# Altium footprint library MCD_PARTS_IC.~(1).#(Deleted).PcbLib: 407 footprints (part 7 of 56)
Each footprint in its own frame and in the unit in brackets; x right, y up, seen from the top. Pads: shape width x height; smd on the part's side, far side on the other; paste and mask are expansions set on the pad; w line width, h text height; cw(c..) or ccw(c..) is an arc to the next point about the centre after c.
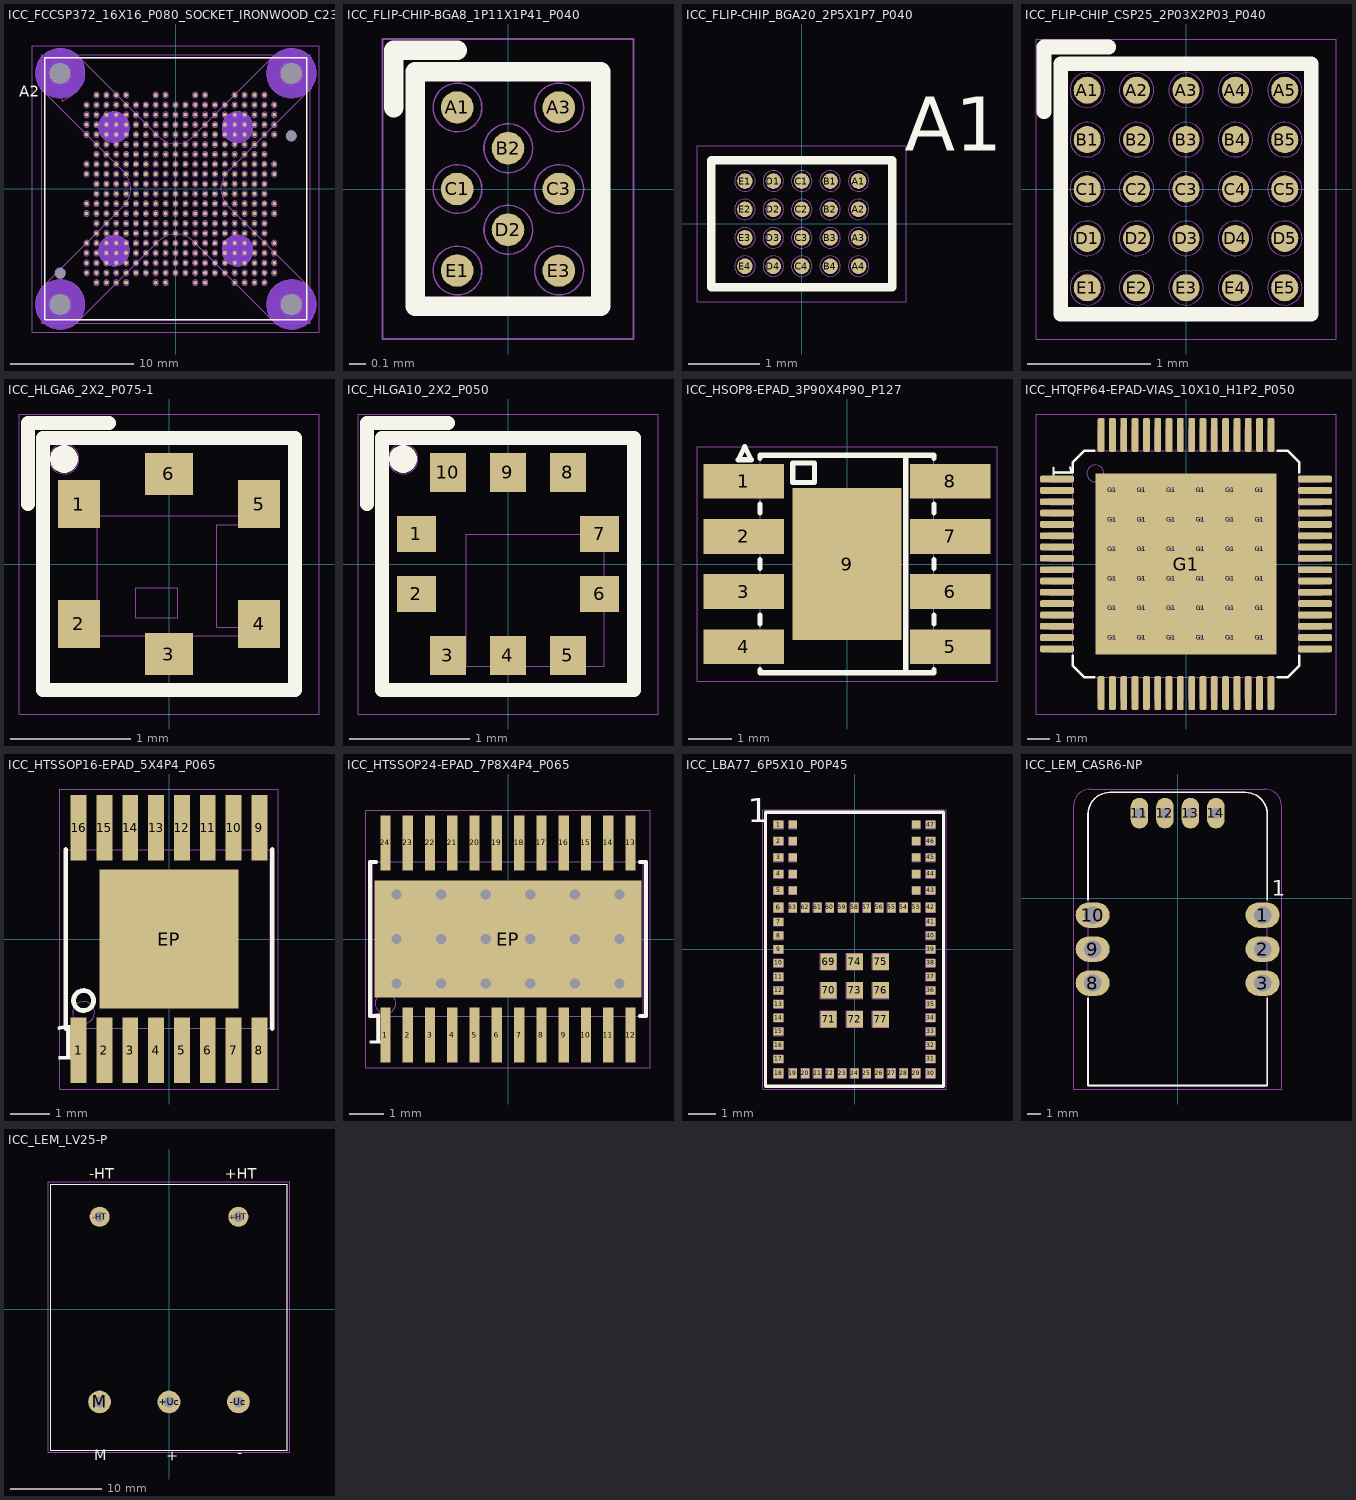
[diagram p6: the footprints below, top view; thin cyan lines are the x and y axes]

## ICC_FCCSP372_16X16_P080_SOCKET_IRONWOOD_C23649 [mm] "MCD-04310"
height 10.13
pads (378):
  round 0.32 smd mask+0.05: A2(-6.425,7.6) A3(-5.625,7.6) A4(-4.825,7.6) A5(-4.025,7.6) A8(-1.625,7.6) A9(-0.825,7.6) A12(1.575,7.6) A13(2.375,7.6) A16(4.775,7.6) A17(5.575,7.6) A18(6.375,7.6) A19(7.175,7.6) B1(-7.225,6.8) B2(-6.425,6.8) B3(-5.625,6.8) B4(-4.825,6.8) B5(-4.025,6.8) B6(-3.225,6.8) B7(-2.425,6.8) B8(-1.625,6.8) B9(-0.825,6.8) B10(-0.025,6.8) B11(0.775,6.8) B12(1.575,6.8) B13(2.375,6.8) B14(3.175,6.8) B15(3.975,6.8) B16(4.775,6.8) B17(5.575,6.8) B18(6.375,6.8) B19(7.175,6.8) B20(7.975,6.8) C1(-7.225,6) C2(-6.425,6) C3(-5.625,6) C4(-4.825,6) C5(-4.025,6) C6(-3.225,6) C7(-2.425,6) C8(-1.625,6) C9(-0.825,6) C10(-0.025,6) C11(0.775,6) C12(1.575,6) C13(2.375,6) C14(3.175,6) C15(3.975,6) C16(4.775,6) C17(5.575,6) C18(6.375,6) C19(7.175,6) C20(7.975,6) D1(-7.225,5.2) D2(-6.425,5.2) D3(-5.625,5.2) D4(-4.825,5.2) D5(-4.025,5.2) D6(-3.225,5.2) D7(-2.425,5.2) D8(-1.625,5.2) D9(-0.825,5.2) D10(-0.025,5.2) D11(0.775,5.2) D12(1.575,5.2) D13(2.375,5.2) D14(3.175,5.2) D15(3.975,5.2) D16(4.775,5.2) D17(5.575,5.2) D18(6.375,5.2) D19(7.175,5.2) D20(7.975,5.2) E1(-7.225,4.4) E2(-6.425,4.4) E3(-5.625,4.4) E4(-4.825,4.4) E5(-4.025,4.4) E6(-3.225,4.4) E7(-2.425,4.4) E8(-1.625,4.4) E9(-0.825,4.4) E10(-0.025,4.4) E11(0.775,4.4) E12(1.575,4.4) E13(2.375,4.4) E14(3.175,4.4) E15(3.975,4.4) E16(4.775,4.4) E17(5.575,4.4) E18(6.375,4.4) E19(7.175,4.4) E20(7.975,4.4) F2(-6.425,3.6) F3(-5.625,3.6) F4(-4.825,3.6) F5(-4.025,3.6) F6(-3.225,3.6) F7(-2.425,3.6) F8(-1.625,3.6) F9(-0.825,3.6) F10(-0.025,3.6) F11(0.775,3.6) F12(1.575,3.6) F13(2.375,3.6) F14(3.175,3.6) F15(3.975,3.6) F16(4.775,3.6) F17(5.575,3.6) F18(6.375,3.6) F19(7.175,3.6) G2(-6.425,2.8) G3(-5.625,2.8) G4(-4.825,2.8) G5(-4.025,2.8) G6(-3.225,2.8) G7(-2.425,2.8) G8(-1.625,2.8) G9(-0.825,2.8) G10(-0.025,2.8) G11(0.775,2.8) G12(1.575,2.8) G13(2.375,2.8) G14(3.175,2.8) G15(3.975,2.8) G16(4.775,2.8) G17(5.575,2.8) G18(6.375,2.8) G19(7.175,2.8) H1(-7.225,2) H2(-6.425,2) H3(-5.625,2) H4(-4.825,2) H5(-4.025,2) H6(-3.225,2) H7(-2.425,2) H8(-1.625,2) H9(-0.825,2) H10(-0.025,2) H11(0.775,2) H12(1.575,2) H13(2.375,2) H14(3.175,2) H15(3.975,2) H16(4.775,2) H17(5.575,2) H18(6.375,2) H19(7.175,2) H20(7.975,2) J1(-7.225,1.2) J2(-6.425,1.2) J3(-5.625,1.2) J4(-4.825,1.2) J5(-4.025,1.2) J6(-3.225,1.2) J7(-2.425,1.2) J8(-1.625,1.2) J9(-0.825,1.2) J10(-0.025,1.2) J11(0.775,1.2) J12(1.575,1.2) J13(2.375,1.2) J14(3.175,1.2) J15(3.975,1.2) J16(4.775,1.2) J17(5.575,1.2) J18(6.375,1.2) J19(7.175,1.2) J20(7.975,1.2) K2(-6.425,0.4) K3(-5.625,0.4) K4(-4.825,0.4) K5(-4.025,0.4) K6(-3.225,0.4) K7(-2.425,0.4) K8(-1.625,0.4) K9(-0.825,0.4) K10(-0.025,0.4) K11(0.775,0.4) K12(1.575,0.4) K13(2.375,0.4) K14(3.175,0.4) K15(3.975,0.4) K16(4.775,0.4) K17(5.575,0.4) K18(6.375,0.4) K19(7.175,0.4) L2(-6.425,-0.4) L3(-5.625,-0.4) L4(-4.825,-0.4) L5(-4.025,-0.4) L6(-3.225,-0.4) L7(-2.425,-0.4) L8(-1.625,-0.4) L9(-0.825,-0.4) L10(-0.025,-0.4) L11(0.775,-0.4) L12(1.575,-0.4) L13(2.375,-0.4) L14(3.175,-0.4) L15(3.975,-0.4) L16(4.775,-0.4) L17(5.575,-0.4) L18(6.375,-0.4) L19(7.175,-0.4) M1(-7.225,-1.2) M2(-6.425,-1.2) M3(-5.625,-1.2) M4(-4.825,-1.2) M5(-4.025,-1.2) M6(-3.225,-1.2) M7(-2.425,-1.2) M8(-1.625,-1.2) M9(-0.825,-1.2) M10(-0.025,-1.2) M11(0.775,-1.2) M12(1.575,-1.2) M13(2.375,-1.2) M14(3.175,-1.2) M15(3.975,-1.2) M16(4.775,-1.2) M17(5.575,-1.2) M18(6.375,-1.2) M19(7.175,-1.2) M20(7.975,-1.2) N1(-7.225,-2) N2(-6.425,-2) N3(-5.625,-2) N4(-4.825,-2) N5(-4.025,-2) N6(-3.225,-2) N7(-2.425,-2) N8(-1.625,-2) N9(-0.825,-2) N10(-0.025,-2) N11(0.775,-2) N12(1.575,-2) N13(2.375,-2) N14(3.175,-2) N15(3.975,-2) N16(4.775,-2) N17(5.575,-2) N18(6.375,-2) N19(7.175,-2) N20(7.975,-2) P2(-6.425,-2.8) P3(-5.625,-2.8) P4(-4.825,-2.8) P5(-4.025,-2.8) P6(-3.225,-2.8) P7(-2.425,-2.8) P8(-1.625,-2.8) P9(-0.825,-2.8) P10(-0.025,-2.8) P11(0.775,-2.8) P12(1.575,-2.8) P13(2.375,-2.8) P14(3.175,-2.8) P15(3.975,-2.8) P16(4.775,-2.8) P17(5.575,-2.8) P18(6.375,-2.8) P19(7.175,-2.8) R2(-6.425,-3.6) R3(-5.625,-3.6) R4(-4.825,-3.6) R5(-4.025,-3.6) R6(-3.225,-3.6) R7(-2.425,-3.6) R8(-1.625,-3.6) R9(-0.825,-3.6) R10(-0.025,-3.6) R11(0.775,-3.6) R12(1.575,-3.6) R13(2.375,-3.6) R14(3.175,-3.6) R15(3.975,-3.6) R16(4.775,-3.6) R17(5.575,-3.6) R18(6.375,-3.6) R19(7.175,-3.6) T1(-7.225,-4.4) T2(-6.425,-4.4) T3(-5.625,-4.4) T4(-4.825,-4.4) T5(-4.025,-4.4) T6(-3.225,-4.4) T7(-2.425,-4.4) T8(-1.625,-4.4) T9(-0.825,-4.4) T10(-0.025,-4.4) T11(0.775,-4.4) T12(1.575,-4.4) T13(2.375,-4.4) T14(3.175,-4.4) T15(3.975,-4.4) T16(4.775,-4.4) T17(5.575,-4.4) T18(6.375,-4.4) T19(7.175,-4.4) T20(7.975,-4.4) U1(-7.225,-5.2) U2(-6.425,-5.2) U3(-5.625,-5.2) U4(-4.825,-5.2) U5(-4.025,-5.2) U6(-3.225,-5.2) U7(-2.425,-5.2) U8(-1.625,-5.2) U9(-0.825,-5.2) U10(-0.025,-5.2) U11(0.775,-5.2) U12(1.575,-5.2) U13(2.375,-5.2) U14(3.175,-5.2) U15(3.975,-5.2) U16(4.775,-5.2) U17(5.575,-5.2) U18(6.375,-5.2) U19(7.175,-5.2) U20(7.975,-5.2) V1(-7.225,-6) V2(-6.425,-6) V3(-5.625,-6) V4(-4.825,-6) V5(-4.025,-6) V6(-3.225,-6) V7(-2.425,-6) V8(-1.625,-6) V9(-0.825,-6) V10(-0.025,-6) V11(0.775,-6) V12(1.575,-6) V13(2.375,-6) V14(3.175,-6) V15(3.975,-6) V16(4.775,-6) V17(5.575,-6) V18(6.375,-6) V19(7.175,-6) V20(7.975,-6) W1(-7.225,-6.8) W2(-6.425,-6.8) W3(-5.625,-6.8) W4(-4.825,-6.8) W5(-4.025,-6.8) W6(-3.225,-6.8) W7(-2.425,-6.8) W8(-1.625,-6.8) W9(-0.825,-6.8) W10(-0.025,-6.8) W11(0.775,-6.8) W12(1.575,-6.8) W13(2.375,-6.8) W14(3.175,-6.8) W15(3.975,-6.8) W16(4.775,-6.8) W17(5.575,-6.8) W18(6.375,-6.8) W19(7.175,-6.8) W20(7.975,-6.8) Y2(-6.425,-7.6) Y3(-5.625,-7.6) Y4(-4.825,-7.6) Y5(-4.025,-7.6) Y8(-1.625,-7.6) Y9(-0.825,-7.6) Y12(1.575,-7.6) Y13(2.375,-7.6) Y16(4.775,-7.6) Y17(5.575,-7.6) Y18(6.375,-7.6) Y19(7.175,-7.6)
  round 0 hole 0.85 unplated mask+0.05: NPTH2(-9.363,-6.823) NPTH2(9.363,4.283)
  round 0 hole 1.71 unplated mask+0.05: PTH1(-9.37,-9.369) PTH1(-9.37,9.356) PTH1(9.355,-9.369) PTH1(9.355,9.356)
Bottom Layer keep-out:
  region: -3.75,5 -3.75,4.877 -3.798,4.635 -3.892,4.408 -4.029,4.203 -4.203,4.029 -4.408,3.892 -4.635,3.798 -4.877,3.75 -5,3.75 -5.123,3.75 -5.365,3.798 -5.592,3.892 -5.797,4.029 -5.971,4.203 -6.108,4.408 -6.202,4.635 -6.25,4.877 -6.25,5 -6.25,5.123 -6.202,5.365 -6.108,5.592 -5.971,5.797 -5.797,5.971 -5.592,6.108 -5.365,6.202 -5.123,6.25 -5,6.25 -4.877,6.25 -4.635,6.202 -4.408,6.108 -4.203,5.971 -4.029,5.797 -3.892,5.592 -3.798,5.365 -3.75,5.123 -3.75,5
  region: 6.25,5 6.25,4.877 6.202,4.635 6.108,4.408 5.971,4.203 5.797,4.029 5.592,3.892 5.365,3.798 5.123,3.75 5,3.75 4.877,3.75 4.635,3.798 4.408,3.892 4.203,4.029 4.029,4.203 3.892,4.408 3.798,4.635 3.75,4.877 3.75,5 3.75,5.123 3.798,5.365 3.892,5.592 4.029,5.797 4.203,5.971 4.408,6.108 4.635,6.202 4.877,6.25 5,6.25 5.123,6.25 5.365,6.202 5.592,6.108 5.797,5.971 5.971,5.797 6.108,5.592 6.202,5.365 6.25,5.123 6.25,5
  region: 6.25,-5 6.25,-5.123 6.202,-5.365 6.108,-5.592 5.971,-5.797 5.797,-5.971 5.592,-6.108 5.365,-6.202 5.123,-6.25 5,-6.25 4.877,-6.25 4.635,-6.202 4.408,-6.108 4.203,-5.971 4.029,-5.797 3.892,-5.592 3.798,-5.365 3.75,-5.123 3.75,-5 3.75,-4.877 3.798,-4.635 3.892,-4.408 4.029,-4.203 4.203,-4.029 4.408,-3.892 4.635,-3.798 4.877,-3.75 5,-3.75 5.123,-3.75 5.365,-3.798 5.592,-3.892 5.797,-4.029 5.971,-4.203 6.108,-4.408 6.202,-4.635 6.25,-4.877 6.25,-5
  region: -3.75,-5 -3.75,-5.123 -3.798,-5.365 -3.892,-5.592 -4.029,-5.797 -4.203,-5.971 -4.408,-6.108 -4.635,-6.202 -4.877,-6.25 -5,-6.25 -5.123,-6.25 -5.365,-6.202 -5.592,-6.108 -5.797,-5.971 -5.971,-5.797 -6.108,-5.592 -6.202,-5.365 -6.25,-5.123 -6.25,-5 -6.25,-4.877 -6.202,-4.635 -6.108,-4.408 -5.971,-4.203 -5.797,-4.029 -5.592,-3.892 -5.365,-3.798 -5.123,-3.75 -5,-3.75 -4.877,-3.75 -4.635,-3.798 -4.408,-3.892 -4.203,-4.029 -4.029,-4.203 -3.892,-4.408 -3.798,-4.635 -3.75,-4.877 -3.75,-5
  region: -7.363,-9.363 -7.363,-9.56 -7.439,-9.946 -7.59,-10.31 -7.809,-10.637 -8.088,-10.916 -8.415,-11.135 -8.779,-11.286 -9.166,-11.363 -9.363,-11.363 -9.371,-11.363 -9.567,-11.363 -9.952,-11.286 -10.314,-11.136 -10.641,-10.918 -10.918,-10.641 -11.136,-10.314 -11.286,-9.952 -11.363,-9.567 -11.363,-9.371 -11.363,-9.365 -11.363,-9.168 -11.286,-8.781 -11.135,-8.416 -10.915,-8.089 -10.637,-7.81 -10.309,-7.59 -9.944,-7.439 -9.557,-7.363 -9.36,-7.363 -9.359,-7.363 -9.163,-7.363 -8.777,-7.439 -8.413,-7.59 -8.086,-7.808 -7.808,-8.086 -7.59,-8.413 -7.439,-8.777 -7.363,-9.163 -7.363,-9.359
  region: -7.355,9.369 -7.355,9.172 -7.432,8.786 -7.583,8.422 -7.802,8.094 -8.081,7.816 -8.408,7.597 -8.772,7.446 -9.158,7.369 -9.355,7.369 -9.364,7.369 -9.56,7.369 -9.945,7.446 -10.307,7.596 -10.633,7.814 -10.911,8.091 -11.129,8.417 -11.279,8.78 -11.355,9.165 -11.355,9.361 -11.355,9.367 -11.355,9.564 -11.279,9.951 -11.128,10.315 -10.908,10.643 -10.629,10.922 -10.302,11.141 -9.937,11.292 -9.55,11.369 -9.353,11.369 -9.352,11.369 -9.156,11.369 -8.77,11.292 -8.406,11.142 -8.079,10.923 -7.801,10.645 -7.583,10.318 -7.432,9.955 -7.355,9.569 -7.355,9.372
  region: 11.37,9.369 11.37,9.172 11.293,8.786 11.142,8.422 10.923,8.094 10.644,7.816 10.317,7.597 9.953,7.446 9.567,7.369 9.37,7.369 9.361,7.369 9.165,7.369 8.78,7.446 8.418,7.596 8.092,7.814 7.814,8.091 7.596,8.417 7.446,8.78 7.37,9.165 7.37,9.361 7.37,9.367 7.37,9.564 7.446,9.951 7.597,10.315 7.817,10.643 8.096,10.922 8.423,11.141 8.788,11.292 9.175,11.369 9.372,11.369 9.373,11.369 9.569,11.369 9.955,11.292 10.319,11.142 10.646,10.923 10.924,10.645 11.142,10.318 11.293,9.955 11.37,9.569 11.37,9.372
  region: 11.362,-9.363 11.362,-9.56 11.286,-9.946 11.135,-10.31 10.916,-10.637 10.637,-10.916 10.31,-11.135 9.946,-11.286 9.559,-11.363 9.362,-11.363 9.354,-11.363 9.158,-11.363 8.773,-11.286 8.411,-11.136 8.084,-10.918 7.807,-10.641 7.589,-10.314 7.439,-9.952 7.362,-9.567 7.362,-9.371 7.362,-9.365 7.362,-9.168 7.439,-8.781 7.59,-8.416 7.81,-8.089 8.088,-7.81 8.416,-7.59 8.781,-7.439 9.168,-7.363 9.365,-7.363 9.366,-7.363 9.562,-7.363 9.948,-7.439 10.312,-7.59 10.639,-7.808 10.917,-8.086 11.135,-8.413 11.286,-8.777 11.362,-9.163 11.362,-9.359
Top Overlay:
  lines w0.12: -10.613,-10.613 -10.613,10.613 10.613,10.613 10.613,-10.613 -10.613,-10.613
  text "A2" at -12.7,7.125 h1.5
Bottom Overlay:
  circle w0.12: c-9.363,9.363 r2.1
  circle w0.12: c9.355,-9.369 r2.1
  circle w0.12: c-9.363,-9.363 r2.1
  circle w0.12: c5,5 r1.35
  circle w0.12: c-4.993,4.987 r1.35
  circle w0.12: c-5,-5 r1.35
  circle w0.12: c5,-5 r1.35
  lines w0.12: 8.869,7.321 cw(c9.363,9.363) 9.781,7.305
M14-Top Assembly:
  drawing of 385 lines, arcs and shapes, not listed
  text "'.Designator'" at -1.625,-0.5 h0.75
  text "A2" at -9.525,6.1 h1.5
M15-Bottom Assembly:
  circle w0.01: c-9.363,-9.363 r0.762
  circle w0.01: c-9.363,9.362 r0.762
  circle w0.01: c9.362,-9.363 r0.762
  circle w0.01: c9.362,9.362 r0.762
  circle w0.01: c-9.363,9.362 r0.975
  circle w0.01: c-9.363,9.362 r2
  circle w0.01: c9.362,-9.363 r2
  circle w0.01: c9.362,-9.363 r0.975
  circle w0.01: c-9.363,-9.363 r0.975
  circle w0.01: c-9.363,-9.363 r2
  circle w0.01: c9.362,9.362 r2
  circle w0.01: c9.362,9.362 r0.975
  circle w0.01: c-5,5 r1.25
  circle w0.01: c-5,-5 r1.25
  circle w0.01: c5,-5 r1.25
  circle w0.01: c5,5 r1.25
  lines w0.01: -10.777,-7.948 -4.243,-1.414 ccw(c-5.657,0) -4.243,1.414 -10.777,7.948 ; -7.948,-10.777 -1.414,-4.243 cw(c0,-5.657) 1.414,-4.243 7.948,-10.777 ; -7.948,10.777 -1.414,4.243 ccw(c0,5.657) 1.414,4.243 7.948,10.777 ; 10.777,-7.948 4.243,-1.414 cw(c5.657,0) 4.243,1.414 10.777,7.948
M16-Top Courtyard:
  lines w0.01: -10.875,-10.875 -10.875,10.875 10.875,10.875 10.875,-10.875 -10.875,-10.875
M17-Bottom Courtyard:
  lines w0.01: -11.625,-11.625 11.6,-11.625 11.6,11.6 -11.625,11.6 -11.625,-11.625
3D body: height 10.13, standoff 0, extent -10.613,-10.613 10.613,10.613
3D body: height 4.18, standoff 0, extent -11.37,7.356 -7.37,11.356
3D body: height 4.18, standoff 0, extent 7.355,7.356 11.355,11.356
3D body: height 4.18, standoff 0, extent 7.355,-11.369 11.355,-7.369
3D body: height 4.18, standoff 0, extent -11.37,-11.369 -7.37,-7.369
3D body: height 1.93, standoff 0, extent -6.243,3.738 -3.743,6.238
3D body: height 1.93, standoff 0, extent 3.75,3.75 6.25,6.25
3D body: height 1.93, standoff 0, extent 3.75,-6.25 6.25,-3.75
3D body: height 1.93, standoff 0, extent -6.25,-6.25 -3.75,-3.75
3D body: height 4.18, standoff 1.93, extent -10.875,-10.875 10.875,10.875

## ICC_FLIP-CHIP-BGA8_1P11X1P41_P040 [mm]
height 0.6
pads (8):
  round 0.2 smd paste+0.025 mask+0.038: A1(-0.312,0.5) A3(0.312,0.5) B2(0,0.25) C1(-0.312,0) C3(0.312,0) D2(0,-0.25) E1(-0.312,-0.5) E3(0.312,-0.5)
Top Overlay:
  lines w0.12: -0.7,0.5 -0.7,0.85 -0.31,0.85 ; -0.57,-0.72 -0.57,0.72 0.57,0.72 0.57,-0.72 -0.57,-0.72
M14-Top Assembly:
  circle w0.01: c-0.31,0.5 r0.15
  circle w0.01: c0.002,0.25 r0.15
  circle w0.01: c0.314,0.5 r0.15
  circle w0.01: c-0.31,0 r0.15
  circle w0.01: c0.314,0 r0.15
  circle w0.01: c0.002,-0.25 r0.15
  circle w0.01: c0.314,-0.5 r0.15
  circle w0.01: c-0.31,-0.5 r0.15
  lines w0.01: -0.57,-0.72 -0.57,0.72 0.57,0.72 0.57,-0.72 -0.57,-0.72
  text "'.Designator'" at 0,0 h0.75
  text "A1" at -0.45,0.4 h0.3
M16-Top Courtyard:
  lines w0.01: -0.77,-0.92 -0.77,0.92 0.77,0.92 0.77,-0.92 -0.77,-0.92
3D body: height 0.24, standoff -0.02, extent -0.434,-0.628 -0.182,-0.372
3D body: height 0.24, standoff -0.02, extent 0.19,-0.628 0.442,-0.372
3D body: height 0.24, standoff -0.02, extent -0.122,-0.378 0.13,-0.122
3D body: height 0.24, standoff -0.02, extent -0.434,-0.128 -0.182,0.128
3D body: height 0.24, standoff -0.02, extent 0.19,-0.128 0.442,0.128
3D body: height 0.24, standoff -0.02, extent -0.122,0.122 0.13,0.378
3D body: height 0.24, standoff -0.02, extent -0.434,0.372 -0.182,0.628
3D body: height 0.24, standoff -0.02, extent 0.19,0.372 0.442,0.628
3D body: height 0.6, standoff 0.23, extent -0.57,-0.72 0.57,0.72
3D body: height 0.61, standoff 0.6, extent -0.441,0.37 -0.182,0.63

## ICC_FLIP-CHIP_BGA20_2P5X1P7_P040 [mm] "MCD-02686"
height 0.6
pads (20):
  round 0.22 smd mask+0.05: A1(0.8,0.6) A2(0.8,0.2) A3(0.8,-0.2) A4(0.8,-0.6) B1(0.4,0.6) B2(0.4,0.2) B3(0.4,-0.2) B4(0.4,-0.6) C1(0,0.6) C2(0,0.2) C3(0,-0.2) C4(0,-0.6) D1(-0.4,0.6) D2(-0.4,0.2) D3(-0.4,-0.2) D4(-0.4,-0.6) E1(-0.8,0.6) E2(-0.8,0.2) E3(-0.8,-0.2) E4(-0.8,-0.6)
Top Overlay:
  lines w0.12: -1.272,-0.895 1.272,-0.895 1.272,0.895 -1.272,0.895 -1.272,-0.895
  text "A1" at 1.45,0.775 h1.3
M14-Top Assembly:
  circle w0.01: c0.4,0.2 r0.145
  circle w0.01: c0,0.2 r0.145
  circle w0.01: c0,0.2 r0.145
  circle w0.01: c0.8,0.2 r0.145
  circle w0.01: c-0.4,0.2 r0.145
  circle w0.01: c-0.8,0.2 r0.145
  circle w0.01: c-0.8,0.6 r0.145
  circle w0.01: c-0.4,0.6 r0.145
  circle w0.01: c0,0.6 r0.145
  circle w0.01: c0.4,0.6 r0.145
  circle w0.01: c0.8,0.6 r0.145
  circle w0.01: c0.8,-0.2 r0.145
  circle w0.01: c0.4,-0.2 r0.145
  circle w0.01: c0,-0.2 r0.145
  circle w0.01: c-0.4,-0.2 r0.145
  circle w0.01: c-0.8,-0.2 r0.145
  circle w0.01: c-0.8,-0.6 r0.145
  circle w0.01: c-0.4,-0.6 r0.145
  circle w0.01: c0,-0.6 r0.145
  circle w0.01: c0.4,-0.6 r0.145
  circle w0.01: c0.8,-0.6 r0.145
  lines w0.01: -1.272,-0.895 1.272,-0.895 1.272,0.895 -1.272,0.895 -1.272,-0.895
  text "'.Designator'" at -2,-0.5 h0.75
  text "A1" at 0.6,0.425 h0.5
M16-Top Courtyard:
  lines w0.01: -1.475,-1.1 -1.475,1.1 1.475,1.1 1.475,-1.1 -1.475,-1.1
3D body: height 0.6, standoff 0.25, extent -1.272,-0.895 1.272,0.895
3D body: height 0.61, standoff 0.6, extent 0.796,0.45 1.095,0.75
3D body: height 0.27, standoff -0.03, extent -0.136,0.457 0.145,0.743
3D body: height 0.27, standoff -0.03, extent 0.264,0.457 0.545,0.743
3D body: height 0.27, standoff -0.03, extent 0.664,0.457 0.945,0.743
3D body: height 0.27, standoff -0.03, extent -0.936,0.057 -0.655,0.343
3D body: height 0.27, standoff -0.03, extent -0.536,0.057 -0.255,0.343
3D body: height 0.27, standoff -0.03, extent -0.136,0.057 0.145,0.343
3D body: height 0.27, standoff -0.03, extent -0.936,0.457 -0.655,0.743
3D body: height 0.27, standoff -0.03, extent -0.936,-0.343 -0.655,-0.057
3D body: height 0.27, standoff -0.03, extent 0.264,0.057 0.545,0.343
3D body: height 0.27, standoff -0.03, extent 0.664,0.057 0.945,0.343
3D body: height 0.27, standoff -0.03, extent -0.536,-0.343 -0.255,-0.057
3D body: height 0.27, standoff -0.03, extent 0.664,-0.743 0.945,-0.457
3D body: height 0.27, standoff -0.03, extent 0.664,-0.343 0.945,-0.057
3D body: height 0.27, standoff -0.03, extent 0.264,-0.343 0.545,-0.057
3D body: height 0.27, standoff -0.03, extent -0.136,-0.343 0.145,-0.057
3D body: height 0.27, standoff -0.03, extent -0.936,-0.743 -0.655,-0.457
3D body: height 0.27, standoff -0.03, extent -0.536,-0.743 -0.255,-0.457
3D body: height 0.27, standoff -0.03, extent -0.136,-0.743 0.145,-0.457
3D body: height 0.27, standoff -0.03, extent 0.264,-0.743 0.545,-0.457
3D body: height 0.27, standoff -0.03, extent -0.536,0.457 -0.255,0.743

## ICC_FLIP-CHIP_CSP25_2P03X2P03_P040 [mm] "MCD-01725"
height 0.66
pads (25):
  round 0.22 smd paste+0.013 mask+0.04: A1(-0.8,0.8) A2(-0.4,0.8) A3(0,0.8) A4(0.4,0.8) A5(0.8,0.8) B1(-0.8,0.4) B2(-0.4,0.4) B3(0,0.4) B4(0.4,0.4) B5(0.8,0.4) C1(-0.8,0) C2(-0.4,0) C3(0,0) C4(0.4,0) C5(0.8,0) D1(-0.8,-0.4) D2(-0.4,-0.4) D3(0,-0.4) D4(0.4,-0.4) D5(0.8,-0.4) E1(-0.8,-0.8) E2(-0.4,-0.8) E3(0,-0.8) E4(0.4,-0.8) E5(0.8,-0.8)
Top Overlay:
  lines w0.12: -1.15,0.625 -1.15,1.15 -0.625,1.15 ; -1.015,-1.015 1.015,-1.015 1.015,1.015 -1.015,1.015 -1.015,-1.015
M14-Top Assembly:
  circle w0.01: c0.8,0.8 r0.14
  circle w0.01: c0.4,0.8 r0.14
  circle w0.01: c0,0.8 r0.14
  circle w0.01: c-0.4,0.8 r0.14
  circle w0.01: c-0.8,0.8 r0.14
  circle w0.01: c-0.8,0.4 r0.14
  circle w0.01: c-0.4,0.4 r0.14
  circle w0.01: c0,0.4 r0.14
  circle w0.01: c0.4,0.4 r0.14
  circle w0.01: c0.8,0.4 r0.14
  circle w0.01: c-0.8,0 r0.14
  circle w0.01: c-0.4,0 r0.14
  circle w0.01: c0,0 r0.14
  circle w0.01: c0.4,0 r0.14
  circle w0.01: c0.8,0 r0.14
  circle w0.01: c-0.8,-0.4 r0.14
  circle w0.01: c-0.4,-0.4 r0.14
  circle w0.01: c0,-0.4 r0.14
  circle w0.01: c0.4,-0.4 r0.14
  circle w0.01: c0.8,-0.4 r0.14
  circle w0.01: c-0.8,-0.8 r0.14
  circle w0.01: c-0.4,-0.8 r0.14
  circle w0.01: c0,-0.8 r0.14
  circle w0.01: c0.4,-0.8 r0.14
  circle w0.01: c0.8,-0.8 r0.14
  lines w0.01: -1.015,-1.015 -1.015,1.015 1.015,1.015 1.015,-1.015 -1.015,-1.015
  text "'.Designator'" at -2,-0.5 h0.75
  text "A1" at -0.975,0.7 h0.35
  text "A5" at 0.625,0.7 h0.35
  text "E1" at -0.95,-0.9 h0.35
  text "E5" at 0.65,-0.9 h0.35
M16-Top Courtyard:
  lines w0.01: -1.215,-1.215 -1.215,1.215 1.215,1.215 1.215,-1.215 -1.215,-1.215
3D body: height 0.26, standoff -0.02, extent 0.669,0.662 0.94,0.938
3D body: height 0.26, standoff -0.02, extent 0.269,0.662 0.54,0.938
3D body: height 0.26, standoff -0.02, extent -0.131,0.662 0.14,0.938
3D body: height 0.26, standoff -0.02, extent -0.531,0.662 -0.26,0.938
3D body: height 0.67, standoff 0.66, extent -0.949,0.65 -0.65,0.95
3D body: height 0.66, standoff 0.22, extent -1.015,-1.015 1.015,1.015
3D body: height 0.26, standoff -0.02, extent -0.931,0.662 -0.66,0.938
3D body: height 0.26, standoff -0.02, extent -0.931,0.262 -0.66,0.538
3D body: height 0.26, standoff -0.02, extent -0.531,0.262 -0.26,0.538
3D body: height 0.26, standoff -0.02, extent -0.131,0.262 0.14,0.538
3D body: height 0.26, standoff -0.02, extent 0.269,0.262 0.54,0.538
3D body: height 0.26, standoff -0.02, extent 0.669,0.262 0.94,0.538
3D body: height 0.26, standoff -0.02, extent -0.931,-0.138 -0.66,0.138
3D body: height 0.26, standoff -0.02, extent -0.531,-0.138 -0.26,0.138
3D body: height 0.26, standoff -0.02, extent -0.131,-0.138 0.14,0.138
3D body: height 0.26, standoff -0.02, extent 0.269,-0.138 0.54,0.138
3D body: height 0.26, standoff -0.02, extent 0.669,-0.138 0.94,0.138
3D body: height 0.26, standoff -0.02, extent -0.931,-0.538 -0.66,-0.262
3D body: height 0.26, standoff -0.02, extent -0.531,-0.538 -0.26,-0.262
3D body: height 0.26, standoff -0.02, extent -0.131,-0.538 0.14,-0.262
3D body: height 0.26, standoff -0.02, extent 0.269,-0.538 0.54,-0.262
3D body: height 0.26, standoff -0.02, extent 0.669,-0.538 0.94,-0.262
3D body: height 0.26, standoff -0.02, extent -0.931,-0.938 -0.66,-0.662
3D body: height 0.26, standoff -0.02, extent -0.531,-0.938 -0.26,-0.662
3D body: height 0.26, standoff -0.02, extent -0.131,-0.938 0.14,-0.662
3D body: height 0.26, standoff -0.02, extent 0.269,-0.938 0.54,-0.662
3D body: height 0.26, standoff -0.02, extent 0.669,-0.938 0.94,-0.662

## ICC_HLGA6_2X2_P075-1 [mm] "MCD-01447"
height 1
pads (6):
  rect 0.35x0.4 smd mask+0.05: 1(-0.75,0.5) 2(-0.75,-0.5) 4(0.75,-0.5) 5(0.75,0.5)
  rect 0.4x0.35 smd mask+0.05: 3(0,-0.75) 6(0,0.75)
Top Overlay:
  circle w0.12: c-0.875,0.875 r0.056
  lines w0.12: -1.175,0.5 -1.175,1.175 -0.5,1.175 ; -1.05,-1.05 -1.05,1.05 1.05,1.05 1.05,-1.05 -1.05,-1.05
M14-Top Assembly:
  circle w0.01: c-0.875,0.875 r0.125
  lines w0.01: 0.6,-0.6 -0.6,-0.6 -0.6,0.4 0.6,0.4 ; 0.6,-0.525 0.4,-0.525 0.4,0.325 0.6,0.325 ; 0.6,0.325 0.6,0.675 0.9,0.675 0.9,0.325 0.6,0.325 ; 0.6,0.4 0.6,0.4 ; -1.05,-1.05 -1.05,1.025 -1.05,1.05 1.05,1.05 1.05,-1.05 -1.05,-1.05 ; -0.9,-0.675 -0.9,-0.325 -0.6,-0.325 -0.6,-0.675 -0.9,-0.675 ; -0.9,0.325 -0.6,0.325 -0.6,0.675 -0.9,0.675 -0.9,0.325 ; -0.275,-0.45 -0.275,-0.2 0.075,-0.2 0.075,-0.45 -0.275,-0.45 ; -0.175,-0.9 0.175,-0.9 0.175,-0.6 -0.175,-0.6 -0.175,-0.9 ; -0.175,0.6 -0.175,0.9 0.175,0.9 0.175,0.6 -0.175,0.6 ; 0.6,-0.675 0.6,-0.325 0.9,-0.325 0.9,-0.675 0.6,-0.675
  text "5" at 0.675,0.375 h0.4
  text "'.Designator'" at -2,-0.5 h0.75
  text "1" at -0.825,0.375 h0.4
  text "2" at -0.825,-0.625 h0.4
  text "3" at -0.075,-0.875 h0.4
  text "4" at 0.675,-0.625 h0.4
  text "6" at -0.075,0.625 h0.4
M16-Top Courtyard:
  lines w0.01: -1.25,-1.25 -1.25,1.25 1.25,1.25 1.25,-1.25 -1.25,-1.25
3D body: height 1.01, standoff 1, extent -1.024,0.725 -0.725,1.025
3D body: height 0.86, standoff 0.85, extent -0.6,-0.5 -0.35,-0.125
3D body: height 1, standoff 0.85, extent -1.05,-1.05 1.05,1.05
3D body: height 1, standoff 0.85, extent -1.05,-0.5 -0.6,-0.125
3D body: height 0.85, standoff 0, extent -1.05,-1.05 1.05,1.05

## ICC_HLGA10_2X2_P050 [mm] "MCD-01449"
height 0.8
pads (10):
  rect 0.325x0.3 smd mask+0.05: 1(-0.763,0.25) 2(-0.763,-0.25) 6(0.763,-0.25) 7(0.763,0.25)
  rect 0.3x0.325 smd mask+0.05: 3(-0.5,-0.762) 4(0,-0.762) 5(0.5,-0.762) 8(0.5,0.763) 9(0,0.763) 10(-0.5,0.763)
Top Overlay:
  circle w0.12: c-0.875,0.875 r0.056
  lines w0.12: -1.175,0.5 -1.175,1.175 -0.5,1.175 ; -1.05,-1.05 1.05,-1.05 1.05,1.05 -1.05,1.05 -1.05,-1.05
M14-Top Assembly:
  circle w0.01: c-0.875,0.875 r0.125
  lines w0.01: -1.05,-1.05 1.05,-1.05 1.05,1.05 -1.05,1.05 -1.05,1.025 -1.05,-1.05 ; -0.9,-0.375 -0.625,-0.375 -0.625,-0.125 -0.9,-0.125 -0.9,-0.375 ; -0.9,0.125 -0.625,0.125 -0.625,0.375 -0.9,0.375 -0.9,0.125 ; -0.625,-0.9 -0.375,-0.9 -0.375,-0.625 -0.625,-0.625 -0.625,-0.9 ; -0.625,0.625 -0.625,0.9 -0.375,0.9 -0.375,0.625 -0.625,0.625 ; -0.35,-0.85 0.8,-0.85 0.8,0.25 -0.35,0.25 -0.35,-0.85 ; -0.125,-0.9 0.125,-0.9 0.125,-0.625 -0.125,-0.625 -0.125,-0.9 ; -0.125,0.625 -0.125,0.9 0.125,0.9 0.125,0.625 -0.125,0.625 ; 0.375,-0.9 0.625,-0.9 0.625,-0.625 0.375,-0.625 0.375,-0.9 ; 0.375,0.625 0.375,0.9 0.625,0.9 0.625,0.625 0.375,0.625 ; 0.625,-0.375 0.9,-0.375 0.9,-0.125 0.625,-0.125 0.625,-0.375 ; 0.625,0.125 0.9,0.125 0.9,0.375 0.625,0.375 0.625,0.125
  text "10" at -0.675,0.625 h0.4
  text "9" at -0.075,0.625 h0.4
  text "8" at 0.425,0.625 h0.4
  text "7" at 0.9,0.175 h0.4
  text "6" at 0.9,-0.35 h0.4
  text "5" at 0.425,-0.9 h0.4
  text "4" at -0.1,-0.9 h0.4
  text "3" at -0.575,-0.9 h0.4
  text "2" at -0.9,-0.175 h0.4
  text "1" at -0.9,0.3 h0.4
  text "'.Designator'" at -2,-0.5 h0.75
M16-Top Courtyard:
  lines w0.01: -1.25,-1.25 1.25,-1.25 1.25,1.25 -1.25,1.25 -1.25,-1.25
3D body "HLGA-10L.STEP": height 0.76, standoff -0.04, extent -1,-1 1,1
3D body: height 0.8, standoff 0, extent -1.05,-1.05 1.05,1.05

## ICC_HSOP8-EPAD_3P90X4P90_P127 [mm]
height 1.7
pads (9):
  rect 1.85x0.8 smd mask+0.05: 1(-2.375,1.905) 2(-2.375,0.635) 3(-2.375,-0.635) 4(-2.375,-1.905) 5(2.375,-1.905) 6(2.375,-0.635) 7(2.375,0.635) 8(2.375,1.905)
  rect 2.5x3.5 smd mask+0.05: 9(0,0)
Top Overlay:
  lines w0.12: -2,-2.425 -2,-2.5 2,-2.5 2,-2.425 ; -2,-1.375 -2,-1.175 ; -2,-0.1 -2,0.1 ; -2,1.175 -2,1.375 ; -2,2.425 -2,2.5 2,2.5 2,2.425 ; 1.35,-2.5 1.35,2.5 ; 2,-1.375 2,-1.175 ; 2,-0.1 2,0.1 ; 2,1.175 2,1.375 ; -2.5,2.4 -2.35,2.7 -2.2,2.4 -2.5,2.4 ; -1.25,1.875 -1.25,2.325 -0.75,2.325 -0.75,1.875 -1.25,1.875
M14-Top Assembly:
  lines w0.01: -2,-2.159 -3.1,-2.159 -3.1,-1.651 -2,-1.651 ; -2,-0.889 -3.1,-0.889 -3.1,-0.381 -2,-0.381 ; -2,0.381 -3.1,0.381 -3.1,0.889 -2,0.889 ; -2,1.651 -3.1,1.651 -3.1,2.159 -2,2.159 ; 1.35,-2.5 1.35,2.5 ; 2,-2.159 3.1,-2.159 3.1,-1.651 2,-1.651 ; 2,-0.889 3.1,-0.889 3.1,-0.381 2,-0.381 ; 2,0.381 3.1,0.381 3.1,0.889 2,0.889 ; 2,1.651 3.1,1.651 3.1,2.159 2,2.159 ; -2,-2.5 -2,2.5 2,2.5 2,-2.5 -2,-2.5 ; -1.1,-1.55 1.1,-1.55 1.1,1.55 -1.1,1.55 -1.1,-1.55
  text "9" at -0.125,-0.225 h0.75
  text "8" at 2.375,1.675 h0.75
  text "5" at 2.375,-2.15 h0.75
  text "4" at -2.725,-2.15 h0.75
  text "1" at -2.55,1.65 h0.75
  text "'.Designator'" at -2,0.25 h0.75
M16-Top Courtyard:
  lines w0.01: -3.45,-2.7 3.45,-2.7 3.45,2.7 -3.45,2.7 -3.45,-2.7
3D body "HSOP8.STEP": height 1.75, standoff 0, extent -3.1,-2.5 3.1,2.5
3D body: height 1.7, standoff 0, extent -2,-2.5 2,2.5

## ICC_HTQFP64-EPAD-VIAS_10X10_H1P2_P050 [mm] "MCD-03608"
height 1.2
pads (101):
  rrect50% 1.5x0.3 smd mask+0.05: 1(-5.7,3.75) 2(-5.7,3.25) 3(-5.7,2.75) 4(-5.7,2.25) 5(-5.7,1.75) 6(-5.7,1.25) 7(-5.7,0.75) 8(-5.7,0.25) 9(-5.7,-0.25) 10(-5.7,-0.75) 11(-5.7,-1.25) 12(-5.7,-1.75) 13(-5.7,-2.25) 14(-5.7,-2.75) 15(-5.7,-3.25) 16(-5.7,-3.75) 33(5.7,-3.75) 34(5.7,-3.25) 35(5.7,-2.75) 36(5.7,-2.25) 37(5.7,-1.75) 38(5.7,-1.25) 39(5.7,-0.75) 40(5.7,-0.25) 41(5.7,0.25) 42(5.7,0.75) 43(5.7,1.25) 44(5.7,1.75) 45(5.7,2.25) 46(5.7,2.75) 47(5.7,3.25) 48(5.7,3.75)
  rrect50% 0.3x1.5 smd mask+0.05: 17(-3.75,-5.7) 18(-3.25,-5.7) 19(-2.75,-5.7) 20(-2.25,-5.7) 21(-1.75,-5.7) 22(-1.25,-5.7) 23(-0.75,-5.7) 24(-0.25,-5.7) 25(0.25,-5.7) 26(0.75,-5.7) 27(1.25,-5.7) 28(1.75,-5.7) 29(2.25,-5.7) 30(2.75,-5.7) 31(3.25,-5.7) 32(3.75,-5.7) 49(3.75,5.7) 50(3.25,5.7) 51(2.75,5.7) 52(2.25,5.7) 53(1.75,5.7) 54(1.25,5.7) 55(0.75,5.7) 56(0.25,5.7) 57(-0.25,5.7) 58(-0.75,5.7) 59(-1.25,5.7) 60(-1.75,5.7) 61(-2.25,5.7) 62(-2.75,5.7) 63(-3.25,5.7) 64(-3.75,5.7)
  round 0.45 hole 0.2 mask+0.05: G1(-3.25,-3.25) G1(-3.25,-1.95) G1(-3.25,-0.65) G1(-3.25,0.65) G1(-3.25,1.95) G1(-3.25,3.25) G1(-1.95,-3.25) G1(-1.95,-1.95) G1(-1.95,-0.65) G1(-1.95,0.65) G1(-1.95,1.95) G1(-1.95,3.25) G1(-0.65,-3.25) G1(-0.65,-1.95) G1(-0.65,-0.65) G1(-0.65,0.65) G1(-0.65,1.95) G1(-0.65,3.25) G1(0.65,-3.25) G1(0.65,-1.95) G1(0.65,-0.65) G1(0.65,0.65) G1(0.65,1.95) G1(0.65,3.25) G1(1.95,-3.25) G1(1.95,-1.95) G1(1.95,-0.65) G1(1.95,0.65) G1(1.95,1.95) G1(1.95,3.25) G1(3.25,-3.25) G1(3.25,-1.95) G1(3.25,-0.65) G1(3.25,0.65) G1(3.25,1.95) G1(3.25,3.25)
  rect 8x8 smd paste-100 mask+0.05: G1(0,0)
Top Overlay:
  lines w0.12: -5,-4.05 -5,-4.5 -4.5,-5 -4.05,-5 ; -5,4.05 -5,4.5 -4.5,5 -4.05,5 ; 4.05,-5 4.5,-5 5,-4.5 5,-4.05 ; 4.05,5 4.5,5 5,4.5 5,4.05
  text "1" at -6.175,4.425 h1.5
Top Paste:
  rectangle: -1.438,-0.437 -0.813,0.437
  rectangle: 0.812,-1.437 1.437,-0.812
  rectangle: -1.438,-1.437 -0.813,-0.812
  rectangle: -0.313,-1.437 0.312,-0.812
  rectangle: -0.437,-0.437 0.437,0.437
  rectangle: 0.812,-0.437 1.437,0.437
  rectangle: -0.313,0.813 0.312,1.438
  rectangle: 0.812,0.813 1.437,1.438
  rectangle: -1.438,0.813 -0.813,1.438
Top Solder:
  rectangle: -1.5,-1.5 1.5,1.5
M14-Top Assembly:
  drawing of 269 lines, arcs and shapes, not listed
  text "G1" at -0.49,-0.32 h1
  text "64" at -4.893,5.184 h1
  text "49" at 3.975,5.184 h1
  text "48" at 5.036,3.986 h1
  text "33" at 5.042,-4.618 h1
  text "32" at 3.964,-5.824 h1
  text "17" at -4.832,-5.821 h1
  text "16" at -5.92,-4.625 h1
  text "'.Designator'" at -2,2 h0.75
  text "1" at -5.61,3.975 h1
M16-Top Courtyard:
  lines w0.01: -6.625,-6.625 0,-6.625 6.625,-6.625 6.625,6.625 0,6.625 -6.625,6.625 -6.625,-6.625
3D body "PAP0064Q.stp": height 1.1, standoff 0, extent -6.015,-6.015 6.015,6.015

## ICC_HTSSOP16-EPAD_5X4P4_P065 [mm]
height 1.2
pads (17):
  rect 0.4x1.65 smd mask+0.05: 1(-2.275,-2.8) 2(-1.625,-2.8) 3(-0.975,-2.8) 4(-0.325,-2.8) 5(0.325,-2.8) 6(0.975,-2.8) 7(1.625,-2.8) 8(2.275,-2.8) 9(2.275,2.8) 10(1.625,2.8) 11(0.975,2.8) 12(0.325,2.8) 13(-0.325,2.8) 14(-0.975,2.8) 15(-1.625,2.8) 16(-2.275,2.8)
  rect 3.5x3.5 smd mask+0.05: EP(0,0)
Top Overlay:
  circle w0.12: c-2.15,-1.55 r0.251
  lines w0.12: -2.6,-2.25 -2.6,2.25 ; 2.6,-2.25 2.6,2.25
  text "1" at -2.925,-3.325 h1.5
M14-Top Assembly:
  circle w0.01: c-2.15,-1.85 r0.276
  lines w0.01: -2.425,-2.25 -2.425,-3.3 -2.125,-3.3 -2.125,-2.25 ; -2.425,2.25 -2.425,3.3 -2.125,3.3 -2.125,2.25 ; -1.775,-2.25 -1.775,-3.3 -1.475,-3.3 -1.475,-2.25 ; -1.775,2.25 -1.775,3.3 -1.475,3.3 -1.475,2.25 ; -1.125,-2.25 -1.125,-3.3 -0.825,-3.3 -0.825,-2.25 ; -1.125,2.25 -1.125,3.3 -0.825,3.3 -0.825,2.25 ; -0.475,-2.25 -0.475,-3.3 -0.175,-3.3 -0.175,-2.25 ; -0.475,2.25 -0.475,3.3 -0.175,3.3 -0.175,2.25 ; 0.175,-2.25 0.175,-3.3 0.475,-3.3 0.475,-2.25 ; 0.175,2.25 0.175,3.3 0.475,3.3 0.475,2.25 ; 0.825,-2.25 0.825,-3.3 1.125,-3.3 1.125,-2.25 ; 0.825,2.25 0.825,3.3 1.125,3.3 1.125,2.25 ; 1.475,-2.25 1.475,-3.3 1.775,-3.3 1.775,-2.25 ; 1.475,2.25 1.475,3.3 1.775,3.3 1.775,2.25 ; 2.125,-2.25 2.125,-3.3 2.425,-3.3 2.425,-2.25 ; 2.125,2.25 2.125,3.3 2.425,3.3 2.425,2.25 ; -2.55,-2.25 2.55,-2.25 2.55,2.25 -2.55,2.25 -2.55,-2.25 ; -1.5,-1.5 -1.5,1.5 1.5,1.5 1.5,-1.5 -1.5,-1.5
  text "'.Designator'" at -2,0.25 h0.75
  text "EP" at -0.4,-0.225 h0.75
  text "16" at -2.6,2.5 h0.75
  text "9" at 2.123,2.518 h0.75
  text "8" at 2.12,-2.978 h0.75
  text "1" at -2.367,-2.993 h0.75
M16-Top Courtyard:
  lines w0.01: -2.75,-3.775 2.75,-3.775 2.75,3.775 -2.75,3.775 -2.75,-3.775
3D body: height 1.2, standoff 0, extent -2.56,-2.26 2.55,2.25
3D body "TSSOP16_5-1X4-5_P065.STEP": height 1, standoff 0, extent -2.5,-3.2 2.5,3.2

## ICC_HTSSOP24-EPAD_7P8X4P4_P065 [mm]
height 1.2
pads (25):
  rect 0.3x1.6 smd mask+0.05: 1(-3.575,-2.8) 2(-2.925,-2.8) 3(-2.275,-2.8) 4(-1.625,-2.8) 5(-0.975,-2.8) 6(-0.325,-2.8) 7(0.325,-2.8) 8(0.975,-2.8) 9(1.625,-2.8) 10(2.275,-2.8) 11(2.925,-2.8) 12(3.575,-2.8) 13(3.575,2.8) 14(2.925,2.8) 15(2.275,2.8) 16(1.625,2.8) 17(0.975,2.8) 18(0.325,2.8) 19(-0.325,2.8) 20(-0.975,2.8) 21(-1.625,2.8) 22(-2.275,2.8) 23(-2.925,2.8) 24(-3.575,2.8)
  rect 7.8x3.4 smd paste-10 mask-10: EP(0,0)
via -0.65,0 diameter 0.6 hole 0.3
via -1.95,0 diameter 0.6 hole 0.3
via -3.25,0 diameter 0.6 hole 0.3
via -3.25,1.3 diameter 0.6 hole 0.3
via -3.25,-1.3 diameter 0.6 hole 0.3
via -1.95,-1.3 diameter 0.6 hole 0.3
via -0.65,-1.3 diameter 0.6 hole 0.3
via 0.65,-1.3 diameter 0.6 hole 0.3
via 1.95,-1.3 diameter 0.6 hole 0.3
via 3.25,-1.3 diameter 0.6 hole 0.3
via 3.25,0 diameter 0.6 hole 0.3
via 1.95,0 diameter 0.6 hole 0.3
via 0.65,0 diameter 0.6 hole 0.3
via -1.95,1.3 diameter 0.6 hole 0.3
via -0.65,1.3 diameter 0.6 hole 0.3
via 0.65,1.3 diameter 0.6 hole 0.3
via 1.95,1.3 diameter 0.6 hole 0.3
via 3.25,1.3 diameter 0.6 hole 0.3
Top Overlay:
  lines w0.12: -3.85,-2.25 -4.025,-2.25 -4.025,2.25 -3.85,2.25 ; 3.85,-2.25 4.025,-2.25 4.025,2.25 3.85,2.25
  text "1" at -4.175,-3.35 h1.5
Top Paste:
  rectangle: -1.625,0.13 -0.975,1.17
  region: -0.78,0.325 -0.78,0.975 -1.82,0.975 -1.82,0.325
  region: 0.52,0.325 0.52,0.975 -0.52,0.975 -0.52,0.325
  region: 1.82,0.325 1.82,0.975 0.78,0.975 0.78,0.325
  region: 1.625,1.17 0.975,1.17 0.975,0.13 1.625,0.13
  region: 0.325,1.17 -0.325,1.17 -0.325,0.13 0.325,0.13
  region: -0.975,-0.13 -1.625,-0.13 -1.625,-1.17 -0.975,-1.17
  region: 0.325,-0.13 -0.325,-0.13 -0.325,-1.17 0.325,-1.17
  region: 1.625,-0.13 0.975,-0.13 0.975,-1.17 1.625,-1.17
  region: 0.78,-0.325 0.78,-0.975 1.82,-0.975 1.82,-0.325
  region: -0.52,-0.325 -0.52,-0.975 0.52,-0.975 0.52,-0.325
  region: -1.82,-0.325 -1.82,-0.975 -0.78,-0.975 -0.78,-0.325
Top Solder:
  rectangle: -2.5,-1.25 2.5,1.25
M14-Top Assembly:
  circle w0.01: c-3.575,-1.875 r0.3
  lines w0.01: -3.95,-2.25 3.95,-2.25 3.95,2.25 -3.95,2.25 -3.95,-2.25 ; -3.675,-3.3 -3.675,-2.25 -3.475,-2.25 -3.475,-3.3 -3.675,-3.3 ; -3.675,2.25 -3.675,3.3 -3.475,3.3 -3.475,2.25 -3.675,2.25 ; -3.025,-3.3 -3.025,-2.25 -2.825,-2.25 -2.825,-3.3 -3.025,-3.3 ; -3.025,2.25 -3.025,3.3 -2.825,3.3 -2.825,2.25 -3.025,2.25 ; -2.435,-1.2 -2.435,1.2 2.435,1.2 2.435,-1.2 -2.435,-1.2 ; -2.375,-3.3 -2.375,-2.25 -2.175,-2.25 -2.175,-3.3 -2.375,-3.3 ; -2.375,2.25 -2.375,3.3 -2.175,3.3 -2.175,2.25 -2.375,2.25 ; -1.725,-3.3 -1.725,-2.25 -1.525,-2.25 -1.525,-3.3 -1.725,-3.3 ; -1.725,2.25 -1.725,3.3 -1.525,3.3 -1.525,2.25 -1.725,2.25 ; -1.075,-3.3 -1.075,-2.25 -0.875,-2.25 -0.875,-3.3 -1.075,-3.3 ; -1.075,2.25 -1.075,3.3 -0.875,3.3 -0.875,2.25 -1.075,2.25 ; -0.425,-3.3 -0.425,-2.25 -0.225,-2.25 -0.225,-3.3 -0.425,-3.3 ; -0.425,2.25 -0.425,3.3 -0.225,3.3 -0.225,2.25 -0.425,2.25 ; 0.225,-3.3 0.225,-2.25 0.425,-2.25 0.425,-3.3 0.225,-3.3 ; 0.225,2.25 0.225,3.3 0.425,3.3 0.425,2.25 0.225,2.25 ; 0.875,-3.3 0.875,-2.25 1.075,-2.25 1.075,-3.3 0.875,-3.3 ; 0.875,2.25 0.875,3.3 1.075,3.3 1.075,2.25 0.875,2.25 ; 1.525,-3.3 1.525,-2.25 1.725,-2.25 1.725,-3.3 1.525,-3.3 ; 1.525,2.25 1.525,3.3 1.725,3.3 1.725,2.25 1.525,2.25 ; 2.175,-3.3 2.175,-2.25 2.375,-2.25 2.375,-3.3 2.175,-3.3 ; 2.175,2.25 2.175,3.3 2.375,3.3 2.375,2.25 2.175,2.25 ; 2.825,-3.3 2.825,-2.25 3.025,-2.25 3.025,-3.3 2.825,-3.3 ; 2.825,2.25 2.825,3.3 3.025,3.3 3.025,2.25 2.825,2.25 ; 3.475,-3.3 3.475,-2.25 3.675,-2.25 3.675,-3.3 3.475,-3.3 ; 3.475,2.25 3.475,3.3 3.675,3.3 3.675,2.25 3.475,2.25
  text "1" at -3.725,-3.025 h1
  text "12" at 3.15,-3 h1
  text "13" at 3.15,2.375 h1
  text "24" at -4.025,2.375 h1
  text "'.Designator'" at -2,-0.5 h0.75
M16-Top Courtyard:
  lines w0.01: -4.15,-3.75 4.15,-3.75 4.15,3.75 -4.15,3.75 -4.15,-3.75
3D body "TSSOP24-EPAD.STEP": height 1.2, standoff 0, extent -3.95,-3.278 3.95,3.278
3D body: height 1.2, standoff 0, extent -3.95,-2.25 3.95,2.25
3D body: height 1.25, standoff 1.2, extent -3.873,-2.174 -3.275,-1.575

## ICC_LBA77_6P5X10_P0P45 [mm] "MCD-02528"
height 1.4
pads (77):
  rect 0.35x0.3 smd mask+0.05: 1(-2.775,4.55) 2(-2.775,3.95) 3(-2.775,3.35) 4(-2.775,2.75) 5(-2.775,2.15) 7(-2.775,1) 8(-2.775,0.5) 9(-2.775,0) 10(-2.775,-0.5) 11(-2.775,-1) 12(-2.775,-1.5) 13(-2.775,-2) 14(-2.775,-2.5) 15(-2.775,-3) 16(-2.775,-3.5) 17(-2.775,-4) 31(2.775,-4) 32(2.775,-3.5) 33(2.775,-3) 34(2.775,-2.5) 35(2.775,-2) 36(2.775,-1.5) 37(2.775,-1) 38(2.775,-0.5) 39(2.775,0) 40(2.775,0.5) 41(2.775,1) 43(2.775,2.15) 44(2.775,2.75) 45(2.775,3.35) 46(2.775,3.95) 47(2.775,4.55)
  rect 0.35x0.35 smd mask+0.05: 6(-2.775,1.525) 18(-2.775,-4.525) 30(2.775,-4.525) 42(2.775,1.525)
  rect 0.3x0.35 smd mask+0.05: 19(-2.25,-4.525) 20(-1.8,-4.525) 21(-1.35,-4.525) 22(-0.9,-4.525) 23(-0.45,-4.525) 24(0,-4.525) 25(0.45,-4.525) 26(0.9,-4.525) 27(1.35,-4.525) 28(1.8,-4.525) 29(2.25,-4.525) 53(2.25,1.525) 54(1.8,1.525) 55(1.35,1.525) 56(0.9,1.525) 57(0.45,1.525) 58(0,1.525) 59(-0.45,1.525) 60(-0.9,1.525) 61(-1.35,1.525) 62(-1.8,1.525) 63(-2.25,1.525)
  rect 0.3x0.3 smd mask+0.05: 48(2.25,4.55) 49(2.25,3.95) 50(2.25,3.35) 51(2.25,2.75) 52(2.25,2.15) 64(-2.25,2.15) 65(-2.25,2.75) 66(-2.25,3.35) 67(-2.25,3.95) 68(-2.25,4.55)
  rect 0.6x0.6 smd mask+0.05: 69(-0.95,-0.45) 70(-0.95,-1.5) 71(-0.95,-2.55) 72(0,-2.55) 73(0,-1.5) 74(0,-0.45) 75(0.95,-0.45) 76(0.95,-1.5) 77(0.95,-2.55)
Top Overlay:
  lines w0.12: -3.25,-5 3.25,-5 3.25,5 -3.25,5 -3.25,-5
  text "1" at -3.9,4.35 h1.5
M14-Top Assembly:
  drawing of 316 lines, arcs and shapes, not listed
  text "77" at 0.675,-2.75 h0.6
  text "75" at 0.675,-0.65 h0.6
  text "74" at -0.275,-0.65 h0.6
  text "72" at -0.25,-2.75 h0.6
  text "71" at -1.225,-2.75 h0.6
  text "69" at -1.225,-0.65 h0.6
  text "68" at -2.35,4.35 h0.6
  text "63" at -2.525,1.325 h0.6
  text "18" at -3.025,-4.75 h0.6
  text "30" at 2.525,-4.75 h0.6
  text "47" at 2.625,4.35 h0.6
  text "1" at -2.875,4.35 h0.6
  text "48" at 1.8,4.35 h0.6
  text "53" at 2,1.3 h0.6
  text "'.Designator'" at -2,-0.1 h0.75
M16-Top Courtyard:
  lines w0.01: -3.35,-5.1 3.35,-5.1 3.35,5.1 -3.35,5.1 -3.35,-5.1
3D body: height 1.4, standoff 0, extent -3.25,-5 3.25,5

## ICC_LEM_CASR6-NP [mm] "MCD-03100"
height 16.5
pads (10):
  oval 2.54x1.9 hole 1.3 mask+0.05: 1(6.35,-1.275) 2(6.35,-3.815) 3(6.35,-6.355) 8(-6.35,-6.355) 9(-6.35,-3.815) 10(-6.35,-1.275)
  oval 1.3x2.3 hole 0.8 mask+0.05: 11(-2.857,6.345) 12(-0.953,6.345) 13(0.953,6.345) 14(2.857,6.345)
Top Overlay:
  lines w0.12: -6.7,-7.5 -6.7,-14.015 6.7,-14.015 6.7,-7.5 ; -6.7,-0.125 -6.7,6.257 cw(c-5.062,6.257) -5.062,7.895 5.062,7.895 cw(c5.062,6.257) 6.7,6.257 6.7,-0.125
  text "1" at 7.025,-0.25 h2
M14-Top Assembly:
  lines w0.01: -6.7,-14.015 6.7,-14.015 6.7,6.257 ccw(c5.062,6.257) 5.062,7.895 -5.062,7.895 ccw(c-5.062,6.257) -6.7,6.257 -6.7,-14.015
  text "14" at 2.175,5.7 h2
  text "13" at 0.25,5.72 h2
  text "12" at -1.675,5.7 h2
  text "11" at -3.425,5.7 h2
  text "10" at -6.425,-1.78 h2
  text "9" at -6.225,-4.48 h2
  text "8" at -6.325,-6.955 h2
  text "3" at 5.975,-6.78 h2
  text "2" at 5.798,-4.35 h2
  text "1" at 6,-1.6 h2
  text "'.Designator'" at -2,-0.5 h0.75
M16-Top Courtyard:
  lines w0.01: -7.775,-14.275 7.775,-14.275 7.775,6.88 ccw(c6.505,6.88) 6.505,8.15 -6.505,8.15 ccw(c-6.505,6.88) -7.775,6.88 -7.775,-14.275
3D body: height 0.25, standoff 0, extent 6.35,-1.275 6.604,-1.021
3D body "CASR 6-15-25-50-NP Blackbox.stp": height 16.6, standoff -3.4, extent -6.85,-14.015 6.85,7.895

## ICC_LEM_LV25-P [mm] "MCD-03099"
height 16.4
pads (5):
  round 2.2 hole 1.1 mask+0.05: +HT(7.62,10.16) -HT(-7.62,10.16)
  round 2.5 hole 1.2 mask+0.05: +Uc(0,-10.16) -Uc(7.62,-10.16) M(-7.62,-10.16)
Top Overlay:
  lines w0.12: -13,-15.475 -13,13.725 13,13.725 13,-15.475 -13,-15.475
  text "-" at 7.475,-16.68 h2
  text "+" at -0.3,-16.979 h2
  text "M" at -8.225,-16.95 h2
  text "+HT" at 6.125,13.925 h2
  text "-HT" at -8.75,13.95 h2
M14-Top Assembly:
  lines w0.01: -13,-15.475 -13,13.725 13,13.725 13,-15.475 -13,-15.475
  text "-HT" at -8.85,9.45 h2
  text "+HT" at 6.325,9.45 h2
  text "-" at 7.45,-10.63 h2
  text "+" at -0.35,-10.829 h2
  text "M" at -8.125,-10.75 h2
  text "'.Designator'" at -2,-0.5 h0.75
M16-Top Courtyard:
  lines w0.01: -13.25,-15.7 -13.25,13.975 13.25,13.975 13.25,-15.7 -13.25,-15.7
3D body "LV25-P.stp": height 16.6, standoff -3.15, extent -13,-15.475 13,13.725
